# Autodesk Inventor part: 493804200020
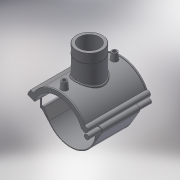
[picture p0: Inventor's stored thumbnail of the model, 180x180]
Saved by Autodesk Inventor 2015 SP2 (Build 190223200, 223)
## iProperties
Created: 2017-07
Part Number: 493804200020
Material: Generic
Description: PLASSON TRANSITION SADDLE 200-2"
Document SubType Name: Modeling
Designer: KIM
Density: 1 g/cm^3
Appearance: Default
Author: KIM
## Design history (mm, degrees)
derived "493804.ipt"
feature "Solid1::493804.ipt"
tag "TaggingFeature1"
body "Solid1"
other parameters: "B_" = 202, "H_" = 76, "L_" = 176, "d_t" = 6, "G_" = 56.656, "d148" = 3, "d160" = 3, "d169" = 3, "d192" = 6, "d2" = 262.6, "d4" = 176, "d5" = 0, "d6" = 0.1, "d8" = 0, "d19" = 6, "d20" = 6, "d21" = 105.6, "d23" = 0, "d24" = 52.8, "d26" = 0, "d27" = 3, "d28" = 3, "d29" = 3, "d30" = 66.66667, "d31" = 6, "d32" = 0, "d33" = 0, "d34" = 0.6, "d40" = 119.6, "d41" = 79.3184, "d43" = 0, "d45" = 0, "d47" = 191, "d48" = 73.6528, "d50" = 0, "d70" = 15, "d72" = 0, "d73" = 6, "d75" = 5, "d76" = 0, "d79" = 15, "d80" = 70.4, "d82" = 5 deg, "d84" = 4, "d85" = 14, "d86" = 0, "d87" = 3, "d88" = 0, "d89" = 1, "d90" = 1, "d91" = 140.8, "d92" = 0, "d93" = 0.5, "d94" = 105.26316, "d96" = 234.6, "d97" = 3.52, "d98" = 0, "d102" = 1.69968, "d103" = 56.656, "d104" = 45.6, "d105" = 0, "d106" = 45.3248, "d108" = 0, "d109" = -25.33333, "d111" = 0.5, "d112" = 0.5, "d113" = 0, "d114" = 0.5, "d117" = 0.56656, "d120" = 140 deg, "d121" = 24.228, "d122" = 20 deg, "d124" = 138, "d126" = 0, "d143" = 206, "d145" = 23.07692, "d149" = 3, "d150" = 25.38462, "d153" = 176, "d154" = 0, "d156" = 115, "d157" = 160 deg, "d159" = 6, "d161" = 3, "d162" = 105.6, "d163" = 0, "d168" = 112.19512, "d170" = 3, "d172" = 0, "d173" = 1, "d176" = 20 deg, "d177" = 14, "d180" = 0, "d183" = 12, "d184" = 11.2, "d185" = 57.2, "d186" = 57.2, "d187" = 115, "d188" = 9, "d189" = 14, "d190" = 0, "d191" = 138, "d193" = 6, "d194" = 4.4, "d195" = 90 deg, "d197" = 0, "d199" = 0
